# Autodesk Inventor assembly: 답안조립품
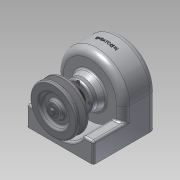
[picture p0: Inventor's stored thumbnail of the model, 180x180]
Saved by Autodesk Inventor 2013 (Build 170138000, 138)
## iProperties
Created: 2015-02
Part Number: 답안조립품
Document SubType Name: Assembly
Designer: Administrator
Author: Administrator
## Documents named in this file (14)
- C:\Users\Administrator\Desktop\450216V1010\답안조립품.iam
- C:\Users\Administrator\Desktop\450216V1010\본체.ipt
- C:\Users\Administrator\Desktop\450216V1010\베어링 6001.ipt
- C:\Users\Administrator\Desktop\450216V1010\축.ipt
- C:\Users\Administrator\Desktop\450216V1010\스퍼기어.ipt
- C:\Users\Administrator\Desktop\450216V1010\키5x5.ipt
- C:\Users\Administrator\Desktop\450216V1010\오일실.ipt
- C:\Users\Administrator\Desktop\450216V1010\축커버.ipt
- C:\Users\Administrator\Desktop\450216V1010\V-벨트풀리.ipt
- C:\Users\Administrator\Desktop\450216V1010\키4x4.ipt
- C:\Users\Administrator\Desktop\450216V1010\M5x0.8.ipt
- M5x0.8.ipt
- C:\Users\Administrator\Desktop\450216V1010\와샤.ipt
- C:\Users\Administrator\Desktop\450216V1010\M3x0.5.ipt
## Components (6 placed, 3 different names)
1. V-벨트풀리:1 — 플러쉬:1, 각도:1
2. M5x0.8:1 — 각도:1
3. M3x0.5:1
4. M3x0.5:2
5. M3x0.5:3
6. M3x0.5:4
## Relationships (2: Flush 1, Angle 1)
- 플러쉬:1 [Flush]: V-벨트풀리:1
- 각도:1 [Angle]: V-벨트풀리:1 ↔ M5x0.8:1
